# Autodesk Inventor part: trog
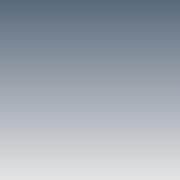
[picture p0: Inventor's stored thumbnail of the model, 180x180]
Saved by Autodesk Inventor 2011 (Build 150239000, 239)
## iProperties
Created: 2010-04
Part Number: trog
Document SubType Name: Modeling
Designer: V.de Jong
Density: 1 g/cm^3
Author: V.de Jong
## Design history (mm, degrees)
node "Blocks"
  sketch "Trog"
    geometry: L1 (0, 0)-(0, -300); L2 (144.181, 0)-(75.071, -275.091); L3 (50.825, -294)-(-50.825, -294); L4 (-75.071, -275.091)-(-144.181, 0); L5 (144.181, 0)-(150, -1.462); L6 (-144.181, 0)-(-150, -1.462); L7 (-144.181, 0)-(144.181, 0); L8 (150, -1.462)-(80.89, -276.553); L9 (50.825, -300)-(-50.825, -300); L10 (-80.89, -276.553)-(-150, -1.462); A1 r 31 centre (50.825, -269) between (50.825, -300) and (80.89, -276.553); A2 r 25 centre (50.825, -269) between (50.825, -294) and (75.071, -275.091); A3 r 25 centre (-50.825, -269) between (-75.071, -275.091) and (-50.825, -294); A4 r 31 centre (-50.825, -269) between (-80.89, -276.553) and (-50.825, -300); 3 further points
    constraints: 20 end point, 8 point on circle, 6 tangent, 4 centre point, 4 point on line, 3 perpendicular, 2 horizontal, 2 midpoint, 1 coincident, 1 equal radius, 1 parallel, 1 vertical alignment, 2 other
    dimensions: "Grootste_Been_Breedte" = 300 distance of L6.end L5.end; "Kleinste_Been_Breedte" = 150 distance of point (75, -300) point (-75, -300); "Min_Radius" = 25 radius of A3; "Plaat_dikte" = 6 distance between parallel lines of L4 L10; "Trog_Hoogte" = 300 distance between parallel lines of L9 L7
